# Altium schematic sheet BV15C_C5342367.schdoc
size 127 x 101 mm
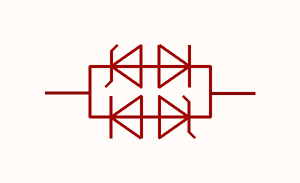
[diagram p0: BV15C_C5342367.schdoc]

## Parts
D?  bv15c_c5342367  [SOD-323_L1.7-W1.3-LS2.5-BI]  (value not drawn)

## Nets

Not connected (* = marked no-connect by the designer): D? 1 2

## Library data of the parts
D? = bv15c_c5342367: 极性:双向;反向截止电压(Vrwm):15V;钳位电压:22V；31V;峰值脉冲电流(Ipp):10A;峰值脉冲功率(Ppp):330W@8/20us;击穿电压(VBR):16V;; Manufacturer: TECH PUBLIC(台舟); ManufacturerPart: BV15C; AddInBom: yes; ModelId: 3c4d3117213c44d8be2b8463c3660d20; ModelTransform: 98.425,51.181,0,0,0,0,-0.001,0.006,0; Polarity: 双向; Reverse Stand-Off Voltage (Vrwm): 15V; Peak Pulse Current (Ipp): 10A; Voltage - Breakdown: 16V; Reverse Leakage Current (Ir): 200nA; Number of Channels: 单路; level of protection: IEC 61000-4-2；IEC 61000-4-4; Type: ESD; Junction Capacitance: 1pF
